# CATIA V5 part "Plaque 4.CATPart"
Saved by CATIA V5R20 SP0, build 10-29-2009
Part number: Plaque 4
Bounding box of the stored display mesh (mm): x -100 to 100, y -200 to 895, z -170 to 230
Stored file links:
  D:\Dropbox\IAO_2011\MMS_GR1\0\video\IAO_2011_1503_rjugie\rjugie\IAO_2011_1503_rjugie\Plaque 4.CATPart
  D:\Dropbox\IAO_2011\MMS_GR1\0\video\IAO_2011_1503_rjugie\rjugie\IAO_2011_1503_rjugie\rjugie.CATProduct
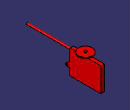
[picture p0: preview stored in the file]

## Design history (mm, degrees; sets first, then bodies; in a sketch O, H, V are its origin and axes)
External parameters (linked from other documents)
  `External.Rayon_extérieur_bielle` = 20 mm
  External.hc = 120 mm
  External.he = 400 mm
  External.Rayon_trou_bielle = 10 mm
  External.vf = 150 mm
  External.Rayon_tige = 15 mm
Set1
  Plane1: stored without definition
Set2
  Plane2: linked copy from another document
  Point1 "E": linked copy from another document
  Plane3: linked copy from another document
Body1 (main body)
  Sketch1 on Plane2, origin (0, 0, 0), H (0, 1, 0), V (0, 0, 1)
    line L1 (445, -170) -> (895, -170)
    line L2 (895, -170) -> (895, 180)
    line L3 (895, 180) -> (445, 180)
    line L4 (445, 180) -> (445, -30)
    line L5 (445, -30) -> (400, -30)
    point P6 (400, -30)
    point P7 (445, -70)
    line L6 (445, -70) -> (445, -170)
    line L7 (445, -70) -> (400, -70)
    point P8 (400, -70)
    reference projected point E1 (400, -50) from Point1
    reference projected point E2 (400, -50) from Point1
    arc A1 centre (400, -50) radius 20 from (400, -30) to (400, -70) ccw
    point P9 (400, -50)
    point P10 (400, -30)
    point P11 (400, -70)
    reference projected point E3 (400, -50) from Point1
    circle A2 centre (400, -50) radius 10
    point P12 (400, -50)
    reference projected point E4 (400, -50) from Point1
    length L3 = 450
    distance L4 V = 445 {= 400mm+25mm+`External.Rayon_extérieur_bielle`}
    distance V P6 = 400 {= External.he}
    distance L5 E1 = 20 {= `External.Rayon_extérieur_bielle`}
    distance L7 E2 = 20 {= `External.Rayon_extérieur_bielle`}
    radius A2 = 10 {= External.Rayon_trou_bielle}
    distance L1 H = 170
    length L2 = 350
    horizontal: L1 H, L3 H, L5 H, L7 H
    vertical: L2 V, L4 V, L6 V
    coincidence: P7 L4, E3 P9, P10 P6, P8 P11, P12 E4
  Pad1: profile Sketch1, direction (1, 0, 0), length 25, opposite side length 25
  Sketch2 on Plane3, origin (0, 0, 0), H (-1, 0, 0), V (0, 0, 1)
    circle A1 centre (0, 150) radius 15
    point P1 (0, 150)
    distance P1 H = 150 {= External.vf}
    distance V P1 = 0
    radius A1 = 15 {= External.Rayon_tige}
  Pad2: profile Sketch2, direction (0, 1, 0), up to the existing solid (limit type 2), opposite side length 200
  Sketch3 on face of Pad1 from Sketch1.L3, origin (0, 0, 180), H (1, 0, 0), V (0, 1, 0)
    circle A1 centre (0, 645) radius 20
    point P1 (0, 645)
    reference projected line E1 (-3, 445) -> (3, 445) from edge [face of Pad1 from Sketch1.L4 | face of Pad1 from Sketch1.L3]
    reference projected line E2 (-25, 895) -> (-25, 445) from edge [start face of Pad1 | face of Pad1 from Sketch1.L3]
    radius A1 = 20
    distance P1 E1 = 200
    distance P1 E2 = 25
  Pad3: profile Sketch3, direction (0, 0, 1), length 50
  Sketch4 on end face of Pad3, origin (0, 0, 230), H (1, 0, 0), V (0, 1, 0)
    circle A1 centre (0, 645) radius 100
    point P1 (0, 645)
    reference projected line E1 (-25, 445) -> (25, 445) from edge [face of Pad1 from Sketch1.L4 | face of Pad1 from Sketch1.L3]
    reference projected line E2 (25, 895) -> (25, 445) from edge [face of Pad1 from Sketch1.L3 | end face of Pad1]
    radius A1 = 100
    distance P1 E1 = 200
    distance E2 P1 = 25
  Pad4: profile Sketch4, direction (0, 0, -1), length 25, opposite side length -10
